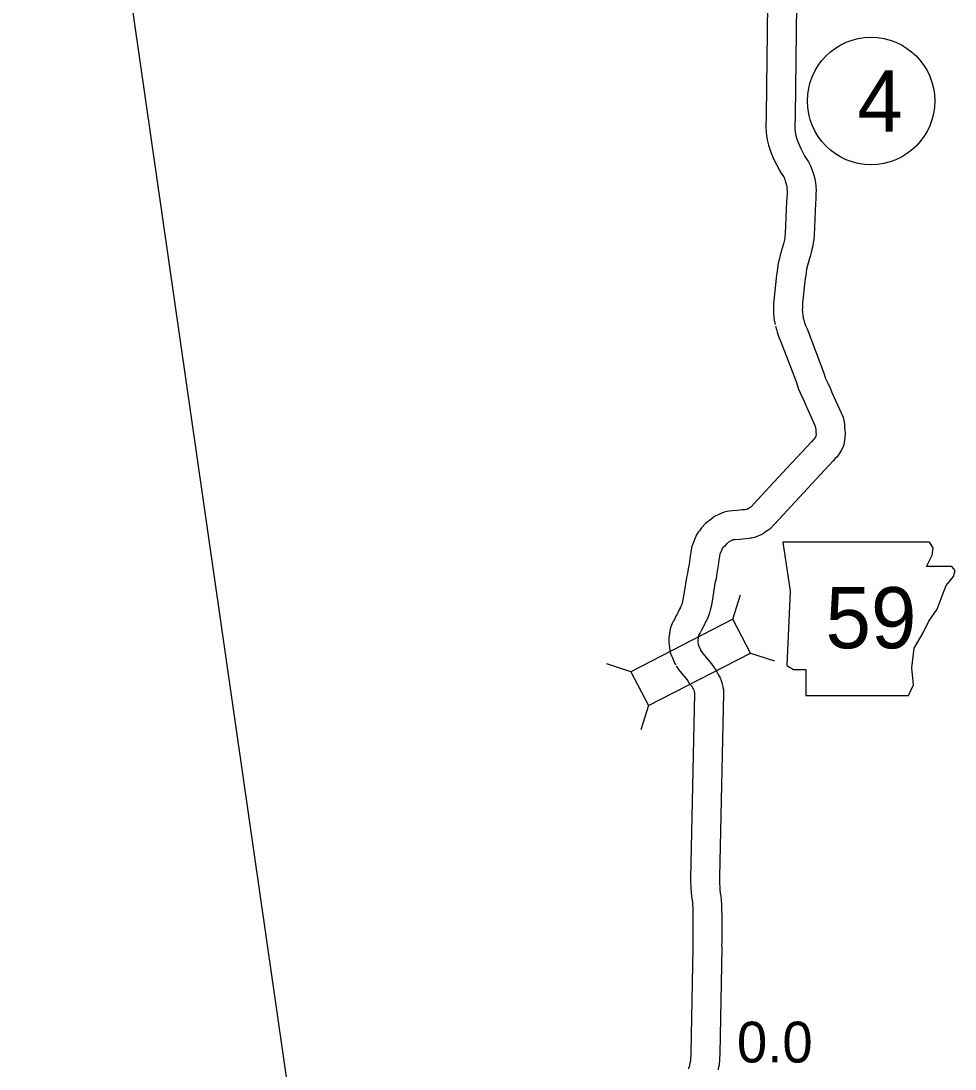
# Model space of a CAD drawing. Extents: x -939622 to -934245, y 1383184 to 1385301.
# Drawn here: x -936492.99 to -936463.94, y 1384855.94 to 1384888.52 of the extents above; entities that cross this region are included whole.
import ezdxf

# ---------------------------------------------------------------- set-up
doc = ezdxf.new("R2010")
doc.units = 0
for name, color, linetype in [('1', 7, 'Continuous'), ('10', 7, 'Continuous'), ('20', 7, 'Continuous'), ('21', 7, 'Continuous'), ('25', 7, 'Continuous'), ('27', 7, 'Continuous')]:
    doc.layers.add(name, color=color, linetype=linetype)

msp = doc.modelspace()

# ---------------------------------------------------------------- linework, layer by layer
at = {"layer": '1'}
msp.add_lwpolyline([(-936484.111, 1384851.453), (-936491.245, 1384900.95), (-936492.986, 1384912.484)], dxfattribs=at)
at = {"layer": '10'}
for points in [[(-936469.725, 1384892.523), (-936469.813, 1384885.591), (-936469.823, 1384885.204), (-936469.81, 1384885.066), (-936469.802, 1384884.959), (-936469.78, 1384884.83), (-936469.74, 1384884.657), (-936469.689, 1384884.506), (-936469.654, 1384884.406), (-936469.599, 1384884.283), (-936469.548, 1384884.171), (-936469.486, 1384884.056), (-936469.451, 1384883.987), (-936469.411, 1384883.894), (-936469.338, 1384883.772), (-936469.266, 1384883.677), (-936469.253, 1384883.65), (-936469.233, 1384883.596), (-936469.216, 1384883.548), (-936469.195, 1384883.477), (-936469.178, 1384883.417), (-936469.171, 1384883.367), (-936469.163, 1384883.308), (-936469.16, 1384883.238), (-936469.162, 1384883.166), (-936469.165, 1384883.02), (-936469.173, 1384882.911), (-936469.219, 1384881.915), (-936469.225, 1384881.832), (-936469.231, 1384881.791), (-936469.245, 1384881.719), (-936469.273, 1384881.592), (-936469.31, 1384881.454), (-936469.343, 1384881.353), (-936469.433, 1384880.989), (-936469.46, 1384880.838), (-936469.472, 1384880.742), (-936469.488, 1384880.632), (-936469.576, 1384879.833), (-936469.582, 1384879.716), (-936469.584, 1384879.641), (-936469.586, 1384879.544), (-936469.584, 1384879.444), (-936469.575, 1384879.318), (-936469.558, 1384879.215), (-936469.535, 1384879.084)], [(-936468.825, 1384892.51), (-936468.913, 1384885.573), (-936468.922, 1384885.233), (-936468.914, 1384885.143), (-936468.908, 1384885.07), (-936468.897, 1384885.007), (-936468.873, 1384884.904), (-936468.838, 1384884.799), (-936468.816, 1384884.737), (-936468.778, 1384884.652), (-936468.742, 1384884.573), (-936468.688, 1384884.473), (-936468.636, 1384884.369), (-936468.609, 1384884.307), (-936468.59, 1384884.275), (-936468.49, 1384884.143), (-936468.423, 1384883.998), (-936468.387, 1384883.902), (-936468.36, 1384883.825), (-936468.331, 1384883.728), (-936468.297, 1384883.609), (-936468.279, 1384883.491), (-936468.266, 1384883.382), (-936468.26, 1384883.248), (-936468.262, 1384883.146), (-936468.266, 1384882.98), (-936468.274, 1384882.861), (-936468.32, 1384881.863), (-936468.329, 1384881.729), (-936468.345, 1384881.632), (-936468.364, 1384881.535), (-936468.398, 1384881.379), (-936468.447, 1384881.197), (-936468.477, 1384881.105), (-936468.552, 1384880.801), (-936468.57, 1384880.705), (-936468.58, 1384880.621), (-936468.596, 1384880.515), (-936468.678, 1384879.763), (-936468.682, 1384879.681), (-936468.684, 1384879.618), (-936468.686, 1384879.541), (-936468.685, 1384879.485), (-936468.68, 1384879.425), (-936468.671, 1384879.366), (-936468.648, 1384879.24)], [(-936469.524, 1384879.038), (-936469.494, 1384878.933), (-936469.468, 1384878.851), (-936469.412, 1384878.695), (-936469.37, 1384878.601), (-936468.879, 1384877.312), (-936468.804, 1384877.071), (-936468.696, 1384876.851), (-936468.642, 1384876.736), (-936468.599, 1384876.623), (-936468.282, 1384875.928), (-936468.272, 1384875.878), (-936468.27, 1384875.824), (-936468.265, 1384875.739), (-936468.26, 1384875.67), (-936468.26, 1384875.656), (-936468.263, 1384875.637), (-936468.27, 1384875.6), (-936468.272, 1384875.595), (-936468.279, 1384875.585), (-936468.399, 1384875.443), (-936469.31, 1384874.463), (-936469.82, 1384873.917), (-936470.066, 1384873.646), (-936470.275, 1384873.42), (-936470.342, 1384873.378), (-936470.374, 1384873.353), (-936470.385, 1384873.348), (-936470.4, 1384873.341), (-936470.436, 1384873.338), (-936470.475, 1384873.329), (-936470.555, 1384873.323), (-936470.712, 1384873.3), (-936470.854, 1384873.293), (-936470.966, 1384873.279), (-936471.083, 1384873.258), (-936471.217, 1384873.213), (-936471.304, 1384873.17), (-936471.393, 1384873.124), (-936471.458, 1384873.085), (-936471.536, 1384873.028), (-936471.576, 1384872.994), (-936471.637, 1384872.954), (-936471.692, 1384872.898), (-936471.818, 1384872.767), (-936471.885, 1384872.674), (-936471.921, 1384872.626), (-936471.975, 1384872.543), (-936472.026, 1384872.421), (-936472.095, 1384872.267), (-936472.132, 1384872.152), (-936472.144, 1384872.061), (-936472.155, 1384872.017), (-936472.162, 1384871.94), (-936472.17, 1384871.893), (-936472.18, 1384871.8), (-936472.208, 1384871.641), (-936472.235, 1384871.496), (-936472.255, 1384871.341), (-936472.284, 1384871.222), (-936472.359, 1384870.769), (-936472.399, 1384870.538), (-936472.423, 1384870.427), (-936472.426, 1384870.412), (-936472.431, 1384870.395), (-936472.439, 1384870.372), (-936472.445, 1384870.357), (-936472.468, 1384870.316), (-936472.48, 1384870.284), (-936472.488, 1384870.271), (-936472.532, 1384870.184), (-936472.555, 1384870.125), (-936472.575, 1384870.084), (-936472.615, 1384870.017), (-936472.664, 1384869.919), (-936472.687, 1384869.875), (-936472.736, 1384869.79), (-936472.77, 1384869.688), (-936472.806, 1384869.579), (-936472.817, 1384869.465), (-936472.838, 1384869.354), (-936472.836, 1384869.214), (-936472.831, 1384869.14), (-936472.821, 1384869.037), (-936472.804, 1384868.967), (-936472.791, 1384868.894), (-936472.753, 1384868.782), (-936472.728, 1384868.72), (-936472.693, 1384868.638), (-936472.626, 1384868.509)], [(-936468.659, 1384879.286), (-936468.633, 1384879.194), (-936468.615, 1384879.138), (-936468.577, 1384879.031), (-936468.539, 1384878.946), (-936468.028, 1384877.607), (-936467.966, 1384877.406), (-936467.883, 1384877.238), (-936467.813, 1384877.085), (-936467.769, 1384876.971), (-936467.418, 1384876.204), (-936467.377, 1384875.985), (-936467.371, 1384875.87), (-936467.367, 1384875.8), (-936467.358, 1384875.694), (-936467.362, 1384875.57), (-936467.375, 1384875.488), (-936467.4, 1384875.349), (-936467.441, 1384875.237), (-936467.479, 1384875.169), (-936467.511, 1384875.113), (-936467.542, 1384875.069), (-936467.609, 1384874.965), (-936467.664, 1384874.919), (-936467.726, 1384874.846), (-936468.652, 1384873.85), (-936469.158, 1384873.308), (-936469.402, 1384873.038), (-936469.694, 1384872.723), (-936469.83, 1384872.636), (-936469.904, 1384872.581), (-936469.995, 1384872.537), (-936470.044, 1384872.514), (-936470.09, 1384872.496), (-936470.173, 1384872.467), (-936470.261, 1384872.449), (-936470.296, 1384872.446), (-936470.341, 1384872.436), (-936470.458, 1384872.428), (-936470.624, 1384872.404), (-936470.776, 1384872.396), (-936470.832, 1384872.389), (-936470.858, 1384872.384), (-936470.873, 1384872.379), (-936470.899, 1384872.366), (-936470.953, 1384872.338), (-936470.96, 1384872.334), (-936470.982, 1384872.318), (-936471.037, 1384872.272), (-936471.057, 1384872.259), (-936471.111, 1384872.183), (-936471.15, 1384872.155), (-936471.159, 1384872.142), (-936471.177, 1384872.119), (-936471.2, 1384872.063), (-936471.251, 1384871.949), (-936471.26, 1384871.886), (-936471.266, 1384871.863), (-936471.269, 1384871.827), (-936471.278, 1384871.771), (-936471.289, 1384871.672), (-936471.322, 1384871.482), (-936471.346, 1384871.356), (-936471.369, 1384871.175), (-936471.402, 1384871.041), (-936471.471, 1384870.621), (-936471.515, 1384870.365), (-936471.541, 1384870.247), (-936471.55, 1384870.201), (-936471.573, 1384870.122), (-936471.594, 1384870.061), (-936471.629, 1384869.973), (-936471.653, 1384869.93), (-936471.669, 1384869.889), (-936471.697, 1384869.841), (-936471.711, 1384869.814), (-936471.728, 1384869.77), (-936471.779, 1384869.66), (-936471.826, 1384869.582), (-936471.865, 1384869.505), (-936471.9, 1384869.44), (-936471.91, 1384869.422), (-936471.916, 1384869.403), (-936471.92, 1384869.392), (-936471.925, 1384869.338), (-936471.937, 1384869.274), (-936471.937, 1384869.251), (-936471.934, 1384869.218), (-936471.931, 1384869.188), (-936471.923, 1384869.151), (-936471.916, 1384869.117), (-936471.91, 1384869.097), (-936471.898, 1384869.069), (-936471.878, 1384869.02), (-936471.827, 1384868.922)], [(-936471.848, 1384868.959), (-936471.809, 1384868.898), (-936471.783, 1384868.861), (-936471.567, 1384868.605), (-936471.483, 1384868.495), (-936471.451, 1384868.441), (-936471.4, 1384868.379), (-936471.347, 1384868.289), (-936471.298, 1384868.204), (-936471.244, 1384868.108), (-936471.209, 1384868.017), (-936471.174, 1384867.921), (-936471.158, 1384867.838), (-936471.153, 1384867.798), (-936471.137, 1384867.738), (-936471.135, 1384867.621), (-936471.266, 1384861.915), (-936471.257, 1384861.851), (-936471.263, 1384861.783), (-936471.258, 1384861.708), (-936471.251, 1384861.603), (-936471.247, 1384861.513), (-936471.239, 1384861.423), (-936471.219, 1384861.317), (-936471.205, 1384861.172), (-936471.204, 1384861.08), (-936471.197, 1384860.978), (-936471.195, 1384860.854), (-936471.194, 1384860.757), (-936471.189, 1384860.625), (-936471.187, 1384860.458), (-936471.188, 1384860.323), (-936471.186, 1384860.214), (-936471.188, 1384860.1), (-936471.186, 1384859.982), (-936471.192, 1384859.884), (-936471.195, 1384859.804), (-936471.194, 1384859.706), (-936471.251, 1384856.422), (-936471.274, 1384856.073), (-936471.299, 1384855.956), (-936471.306, 1384855.916)], [(-936472.605, 1384868.472), (-936472.553, 1384868.391), (-936472.493, 1384868.308), (-936472.27, 1384868.043), (-936472.232, 1384867.992), (-936472.19, 1384867.921), (-936472.137, 1384867.858), (-936472.124, 1384867.835), (-936472.08, 1384867.759), (-936472.061, 1384867.724), (-936472.052, 1384867.702), (-936472.045, 1384867.683), (-936472.038, 1384867.627), (-936472.035, 1384867.617), (-936472.167, 1384861.867), (-936472.162, 1384861.829), (-936472.167, 1384861.772), (-936472.16, 1384861.707), (-936472.156, 1384861.648), (-936472.149, 1384861.549), (-936472.145, 1384861.453), (-936472.131, 1384861.303), (-936472.112, 1384861.193), (-936472.105, 1384861.123), (-936472.104, 1384861.041), (-936472.096, 1384860.939), (-936472.095, 1384860.841), (-936472.093, 1384860.734), (-936472.089, 1384860.602), (-936472.087, 1384860.456), (-936472.088, 1384860.321), (-936472.086, 1384860.214), (-936472.088, 1384860.1), (-936472.086, 1384860.002), (-936472.09, 1384859.932), (-936472.096, 1384859.82), (-936472.094, 1384859.708), (-936472.151, 1384856.459), (-936472.168, 1384856.195), (-936472.183, 1384856.125), (-936472.192, 1384856.069), (-936472.198, 1384856.038), (-936472.202, 1384856.022), (-936472.204, 1384856.015), (-936472.213, 1384855.993), (-936472.227, 1384855.956), (-936472.234, 1384855.942)]]:
    msp.add_lwpolyline(points, dxfattribs=at)
at = {"layer": '20'}
for p, q in [((-936470.848, 1384869.929), (-936470.607, 1384870.683)), ((-936470.302, 1384868.873), (-936469.548, 1384868.633)), ((-936474.014, 1384868.293), (-936474.769, 1384868.534)), ((-936473.469, 1384867.238), (-936473.71, 1384866.483))]:
    msp.add_line(p, q, dxfattribs=at)
msp.add_lwpolyline([(-936470.848, 1384869.929), (-936474.014, 1384868.293), (-936473.469, 1384867.238), (-936470.302, 1384868.873)], close=True, dxfattribs=at)
at = {"layer": '21'}
msp.add_lwpolyline([(-936469.291, 1384872.323), (-936469.062, 1384870.8), (-936469.164, 1384868.491), (-936468.961, 1384868.364), (-936468.58, 1384868.364), (-936468.58, 1384867.552), (-936465.383, 1384867.552), (-936465.23, 1384867.882), (-936465.281, 1384868.415), (-936465.205, 1384869.024), (-936464.926, 1384869.506), (-936464.748, 1384869.861), (-936464.495, 1384870.242), (-936464.342, 1384870.648), (-936464.215, 1384870.978), (-936463.987, 1384871.257), (-936463.936, 1384871.434), (-936464.038, 1384871.561), (-936464.824, 1384871.561), (-936464.647, 1384871.917), (-936464.621, 1384872.145), (-936464.727, 1384872.32)], close=True, dxfattribs=at)
at = {"layer": '27'}
msp.add_circle((-936466.548, 1384886.032), 1.98, dxfattribs=at)

# ---------------------------------------------------------------- texts
at = {"layer": '21'}
msp.add_text('59', height=1.9008, dxfattribs=at).set_placement((-936467.965, 1384869.021))
at = {"layer": '25'}
msp.add_text('0.0', height=1.2672, dxfattribs=at).set_placement((-936470.72, 1384856.147))
at = {"layer": '27'}
msp.add_text('4', height=1.901, rotation=359.9, dxfattribs=at).set_placement((-936466.975, 1384885.082))

doc.saveas('drawing.dxf')
